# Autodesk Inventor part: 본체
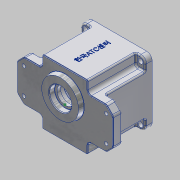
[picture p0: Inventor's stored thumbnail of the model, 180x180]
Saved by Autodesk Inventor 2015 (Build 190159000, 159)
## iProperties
Created: 2016-02
Part Number: 본체
Material: Aluminum 6061
Document SubType Name: Modeling
Designer: Administrator
Density: 2.7 g/cm^3
Appearance: Aluminum - Flat
Mass: 873.755 g
Surface Area: 761.301 cm^2
Volume: 323.613 cm^3
Author: Administrator
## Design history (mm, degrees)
sketch "Sketch1"
  geometry: L1 (33, -47)-(-33, -47); L2 (-33, -47)-(-33, 47); L3 (-33, 47)-(33, 47); L4 (33, 47)-(33, -47); L5 (33, -47)-(-33, 47); L6 (-33, -47)-(33, 47); L7 (70, -30)-(-70, -30); L8 (-70, -30)-(-70, 30); L9 (-70, 30)-(70, 30); L10 (70, 30)-(70, -30); L11 (70, -30)-(-70, 30); L12 (-70, -30)-(70, 30); 1 further point
  constraints: 24 end point, 4 midpoint, 4 parallel, 2 horizontal, 2 perpendicular
  dimensions: "d0" = 66 distance of L2.end L3.end; "d1" = 94 distance of L1.end L2.end; "d2" = 140 distance of L8.end L9.end; "d3" = 60 distance of L7.end L8.end
extrude "Extrusion1" new body sketch "Sketch1" distance "d4" = 13; taper "d5" = 0 deg
extrude "Extrusion2" cut sketch "Sketch1" distance "d6" = 70; taper "d7" = 0 deg
extrude "Extrusion3" join sketch "Sketch1" distance "d8" = 70; taper "d9" = 0 deg
sketch "Sketch2"
  geometry: L1 (47, 47)-(-47, 47); L2 (-47, 47)-(-47, -47); L3 (-47, -47)-(47, -47); L4 (47, -47)-(47, 47); L5 (47, 47)-(-47, -47); L6 (-47, 47)-(47, -47); 1 further point
  constraints: 12 end point, 2 midpoint, 2 parallel, 1 horizontal, 1 perpendicular
  dimensions: "d10" = 94 distance of L3.end L2.end; "d11" = 94 distance of L2.end L1.end
extrude "Extrusion4" join sketch "Sketch2" distance "d12" = 10; taper "d13" = 0 deg; dims "d14" = 57, "d15" = 0
sketch "Sketch3"
  geometry: L1 (-33, 30)-(-70, 30) reference; L2 (-70, 30)-(-70, -30) reference; L3 (-70, -30)-(-33, -30) reference; L4 (-33, -30)-(-33, -47) reference; L5 (-33, -47)-(33, -47) reference; L6 (33, -47)-(33, -30) reference; L7 (33, -30)-(70, -30) reference; L8 (70, -30)-(70, 30) reference; L9 (70, 30)-(33, 30) reference; L10 (33, 30)-(33, 47) reference; L11 (33, 47)-(-33, 47) reference; L12 (-33, 47)-(-33, 30) reference; L13 (-47, 30)-(-33, 30) reference; L14 (-33, 47)-(-33, 30) reference; L15 (-33, 47)-(-47, 47) reference; L16 (-47, 47)-(-47, 30) reference; L17 (33, 30)-(33, 47) reference; L18 (33, 30)-(47, 30) reference; L19 (47, 30)-(47, 47) reference; L20 (47, 47)-(33, 47) reference; L21 (47, -30)-(33, -30) reference; L22 (33, -47)-(33, -30) reference; L23 (33, -47)-(47, -47) reference; L24 (47, -47)-(47, -30) reference; L25 (-33, -30)-(-47, -30) reference; L26 (-47, -30)-(-47, -47) reference; L27 (-47, -47)-(-33, -47) reference; L28 (-33, -30)-(-33, -47) reference; L29 (-47, 47)-(-33, 47); L30 (-33, 47)-(-33, 30); L31 (-33, 30)-(-47, 30); L32 (-47, 30)-(-47, 47); L33 (33, 47)-(47, 47); L34 (47, 47)-(47, 30); L35 (47, 30)-(33, 30); L36 (33, 30)-(33, 47); L37 (33, -30)-(47, -30); L38 (47, -30)-(47, -47); L39 (47, -47)-(33, -47); L40 (33, -47)-(33, -30); L41 (-47, -30)-(-33, -30); L42 (-33, -30)-(-33, -47); L43 (-33, -47)-(-47, -47); L44 (-47, -47)-(-47, -30); 1 further point
  constraints: 32 end point, 8 parallel, 4 horizontal, 4 perpendicular
extrude "Extrusion5" cut sketch "Sketch3" distance "d16" = 57; taper "d17" = 0 deg
sketch "Sketch6"
  geometry: 2 further points
  constraints: 1 coincident
hole "Hole1" sketch "Sketch6" at (0, 0) diameter "d18" = 80; stored, may be unused: countersink angle "d22" = 90 deg, drill point angle "d24" = 0 deg; dims "d19" = 6, "d20" = 86, "d21" = 9, "d23" = 71
sketch "Sketch7"
  geometry: C1 r 43 at (0, 0) reference; A1 r 21 centre (0, -11) between (-8.978, 7.984) and (8.978, 7.984); A2 r 15 centre (0, 20) between (8.978, 7.984) and (-8.978, 7.984); 1 further point
  constraints: 4 point on circle, 2 centre point, 2 vertical alignment
  dimensions: "d25" = 21 radius of A1; "d26" = 11 distance of point (0, 0) A1.centre; "d27" = 15 radius of A2; "d28" = 20 distance of point (0, 0) A2.centre
extrude "Extrusion6" join sketch "Sketch7" distance "d29" = 7; taper "d30" = 0 deg
sketch "Sketch8"
  geometry: A1 r 15 centre (0, 20) between (8.978, 7.984) and (-8.978, 7.984) reference; A2 r 21 centre (0, -11) between (-8.978, 7.984) and (8.978, 7.984) reference; 2 further points
  constraints: 1 coincident
hole "Hole2" sketch "Sketch8" at (0, -11) diameter "d31" = 25; stored, may be unused: countersink angle "d35" = 90 deg, drill point angle "d37" = 0 deg; dims "d32" = 6, "d33" = 35, "d34" = 10, "d36" = 15
sketch "Sketch10"
  geometry: C1 r 17.5 at (0, -11) reference; A1 r 15 centre (0, 20) between (8.978, 7.984) and (-8.978, 7.984) reference; A2 r 21 centre (0, -11) between (-8.978, 7.984) and (8.978, 7.984) reference; 2 further points
  constraints: 1 coincident
hole "Hole3" sketch "Sketch10" at (0, 20) diameter "d41" = 19; stored, may be unused: countersink angle "d45" = 90 deg, drill point angle "d47" = 0 deg; dims "d42" = 6, "d43" = 22, "d44" = 7, "d46" = 8
sketch "Sketch11"
  geometry: C1 r 28 at (0, 11); A1 r 21 centre (0, 11) between (8.978, -7.984) and (-8.978, -7.984) reference; 1 further point
  constraints: 1 centre point, 1 coincident
  dimensions: "d48" = 56 diameter of C1
extrude "Extrusion8" join sketch "Sketch11" distance "d49" = 7; taper "d50" = -10 deg
sketch "Sketch12"
  geometry: C1 r 26.766 at (0, 0) reference; C2 r 16 at (0, 0); 1 further point
  constraints: 1 centre point, 1 coincident
  dimensions: "d51" = 32 diameter of C2
extrude "Extrusion9" cut sketch "Sketch12" distance "d52" = 8; taper "d53" = 0 deg
sketch "Sketch13"
  geometry: C1 r 43 at (0, 0) reference; A1 r 36 centre (0, 0) between (36, 0) and (-36, 0); A2 r 4 centre (36, 0) between (35.852, 3.997) and (35.852, -3.997); A3 r 4 centre (-36, 0) between (-35.852, -3.997) and (-35.852, 3.997); A4 r 40 centre (0, 0) between (39.148, -8.214) and (39.148, 8.214) reference; A5 r 3.5 centre (35.722, -7.495) between (39.148, -8.214) and (35.778, -3.995); A6 r 3.5 centre (35.722, 7.495) between (35.778, 3.995) and (39.148, 8.214); A7 r 3.5 centre (-35.722, -7.495) between (-35.778, -3.995) and (-39.148, -8.214); A8 r 3.5 centre (-35.722, 7.495) between (-39.148, 8.214) and (-35.778, 3.995); A9 r 40 centre (0, 0) between (39.148, -8.214) and (39.148, 8.214); A10 r 40 centre (0, 0) between (-39.148, 8.214) and (-39.148, -8.214); 1 further point
  constraints: 30 point on circle, 9 centre point, 8 tangent, 3 coincident, 2 horizontal alignment
  dimensions: "d54" = 36 radius of A1; "d55" = 4 radius of A2; "d56" = 4 radius of A3; "d57" = 3.5 radius of A5; "d58" = 3.5 radius of A6; "d59" = 3.5 radius of A7; "d60" = 3.5 radius of A8
extrude "Extrusion10" join sketch "Sketch13" stored distance "d61" = 8; taper "d62" = 0 deg
sketch "Sketch14" dims "d0" = 66, "d1" = 94
  geometry: L1 (66, 0)-(0, 0) reference; L2 (-14, 80)-(80, 80) reference; 3 further points
  constraints: 1 midpoint, 1 vertical alignment, 1 other
  dimensions: "d63" = 40 distance from line of L2 point (33, 40)
emboss "Emboss1" sketch "Sketch14" dims "d64" = 0.5, "d65" = 0
chamfer "Chamfer1" distance "d66" = 10; stored, may be unused: second distance "d67" = 2, angle "d68" = 45 deg
fillet "Fillet1" dims "d69" = 5
fillet "Fillet2" dims "d70" = 8
fillet "Fillet3" dims "d71" = 5
sketch "Sketch17"
  geometry: L1 (-68.536, 21.464)-(-61.464, 28.536) reference; L2 (-70, 17.929)-(-70, -17.929) reference; L3 (-61.464, -28.536)-(-68.536, -21.464) reference; L4 (-57.929, -30)-(-38, -30) reference; L5 (-33, -35)-(-33, -47) reference; L6 (-33, -47)-(33, -47) reference; L7 (33, -47)-(33, -35) reference; L8 (38, -30)-(57.929, -30) reference; L9 (68.536, -21.464)-(61.464, -28.536) reference; L10 (70, -17.929)-(70, 17.929) reference; L11 (61.464, 28.536)-(68.536, 21.464) reference; L12 (57.929, 30)-(38, 30) reference; L13 (33, 35)-(33, 47) reference; L14 (33, 47)-(-33, 47) reference; L15 (-33, 47)-(-33, 35) reference; L16 (-38, 30)-(-57.929, 30) reference; L17 (-60.757, 27.828)-(-67.828, 20.757); L18 (-69, 17.929)-(-69, -17.929); L19 (-67.828, -20.757)-(-60.757, -27.828); L20 (-57.929, -29)-(-38, -29); L21 (-32, -35)-(-32, -46); L22 (-32, -46)-(32, -46); L23 (32, -46)-(32, -35); L24 (38, -29)-(57.929, -29); L25 (60.757, -27.828)-(67.828, -20.757); L26 (69, -17.929)-(69, 17.929); L27 (67.828, 20.757)-(60.757, 27.828); L28 (57.929, 29)-(38, 29); L29 (32, 35)-(32, 46); L30 (32, 46)-(-32, 46); L31 (-32, 46)-(-32, 35); L32 (-38, 29)-(-57.929, 29); C1 r 28 at (0, 11) reference; A1 r 5 centre (-57.929, 25) between (-57.929, 30) and (-61.464, 28.536) reference; A2 r 5 centre (-65, 17.929) between (-68.536, 21.464) and (-70, 17.929) reference; A3 r 5 centre (-65, -17.929) between (-70, -17.929) and (-68.536, -21.464) reference; A4 r 5 centre (-57.929, -25) between (-61.464, -28.536) and (-57.929, -30) reference; A5 r 5 centre (-38, -35) between (-33, -35) and (-38, -30) reference; A6 r 5 centre (38, -35) between (38, -30) and (33, -35) reference; A7 r 5 centre (57.929, -25) between (57.929, -30) and (61.464, -28.536) reference; A8 r 5 centre (65, -17.929) between (68.536, -21.464) and (70, -17.929) reference; A9 r 5 centre (65, 17.929) between (70, 17.929) and (68.536, 21.464) reference; A10 r 5 centre (57.929, 25) between (61.464, 28.536) and (57.929, 30) reference; A11 r 5 centre (38, 35) between (33, 35) and (38, 30) reference; A12 r 5 centre (-38, 35) between (-38, 30) and (-33, 35) reference; A13 r 4 centre (-57.929, 25) between (-57.929, 29) and (-60.757, 27.828); A14 r 4 centre (-65, 17.929) between (-67.828, 20.757) and (-69, 17.929); A15 r 4 centre (-65, -17.929) between (-69, -17.929) and (-67.828, -20.757); A16 r 4 centre (-57.929, -25) between (-60.757, -27.828) and (-57.929, -29); A17 r 6 centre (-38, -35) between (-32, -35) and (-38, -29); A18 r 6 centre (38, -35) between (38, -29) and (32, -35); A19 r 4 centre (57.929, -25) between (57.929, -29) and (60.757, -27.828); A20 r 4 centre (65, -17.929) between (67.828, -20.757) and (69, -17.929); A21 r 4 centre (65, 17.929) between (69, 17.929) and (67.828, 20.757); A22 r 4 centre (57.929, 25) between (60.757, 27.828) and (57.929, 29); A23 r 6 centre (38, 35) between (32, 35) and (38, 29); A24 r 6 centre (-38, 35) between (-38, 29) and (-32, 35); 1 further point
  constraints: 32 end point, 24 point on circle, 12 centre point, 27 other
  dimensions: "d75" = 1 distance between parallel lines of L16 L32
extrude "Extrusion12" cut sketch "Sketch17" distance "d76" = 1; taper "d77" = 0 deg
sketch "Sketch19"
  geometry: L1 (60, 19)-(-60, 19); L2 (-60, 19)-(-60, -19); L3 (-60, -19)-(60, -19); L4 (60, -19)-(60, 19); L5 (60, 19)-(-60, -19); L6 (-60, 19)-(60, -19); 5 further points
  constraints: 12 end point, 4 coincident, 2 midpoint, 2 parallel, 1 horizontal, 1 perpendicular
  dimensions: "d80" = 120 distance of L3.end L2.end; "d81" = 38 distance of L2.end L1.end
hole "Hole4" sketch "Sketch19" at (60, -19), (60, 19), (-60, -19), (-60, 19) diameter "d82" = 5; stored, may be unused: countersink angle "d86" = 90 deg, drill point angle "d88" = 0 deg; dims "d83" = 6, "d84" = 9, "d85" = 4, "d87" = 13
sketch "Sketch20"
  geometry: L1 (-40, -40)-(40, -40); L2 (40, -40)-(40, 40); L3 (40, 40)-(-40, 40); L4 (-40, 40)-(-40, -40); L5 (-40, -40)-(40, 40); L6 (40, -40)-(-40, 40); 5 further points
  constraints: 12 end point, 4 coincident, 2 midpoint, 2 parallel, 1 horizontal, 1 perpendicular
  dimensions: "d89" = 80 distance of L3.end L2.end; "d90" = 80 distance of L2.end L1.end
hole "Hole5" sketch "Sketch20" at (-40, 40), (-40, -40), (40, -40), (40, 40) diameter "d91" = 7; stored, may be unused: countersink angle "d95" = 90 deg, drill point angle "d97" = 0 deg; dims "d92" = 6, "d93" = 9, "d94" = 4, "d96" = 10
sketch "Sketch21"
  geometry: A1 r 36 centre (0, 0) between (36, 0) and (-36, 0); 1 further point
  constraints: 2 horizontal alignment, 2 point on circle, 1 centre point, 1 coincident
  dimensions: "d98" = 36 radius of A1
hole "Hole6" sketch "Sketch21" at (36, 0), (-36, 0) diameter "d99" = 3.242; stored, may be unused: countersink angle "d103" = 90 deg, drill point angle "d105" = 118 deg; dims "d100" = 7, "d101" = 9, "d102" = 4, "d104" = 9
sketch "Sketch23"
  geometry: 1 further point
fillet "Fillet5" dims "d107" = 0.3
fillet "Fillet6" dims "d108" = 3
chamfer "Chamfer2" distance "d109" = 1; stored, may be unused: second distance "d110" = 2, angle "d111" = 45 deg
fillet "Fillet7" dims "d112" = 2
fillet "Fillet8" dims "d113" = 2
sketch "Sketch24"
  geometry: 1 further point
fillet "Fillet9" dims "d114" = 2
fillet "Fillet10" dims "d115" = 0.3
body "Solid1"
node "Projected Loop1"
node "Projected Loop2"
node "Projected Loop3"
node "Projected Loop4"
node "Projected Loop5"
node "Projected Loop6"
node "Projected Loop7"
node "Projected Loop8"
node "Projected Loop10"
